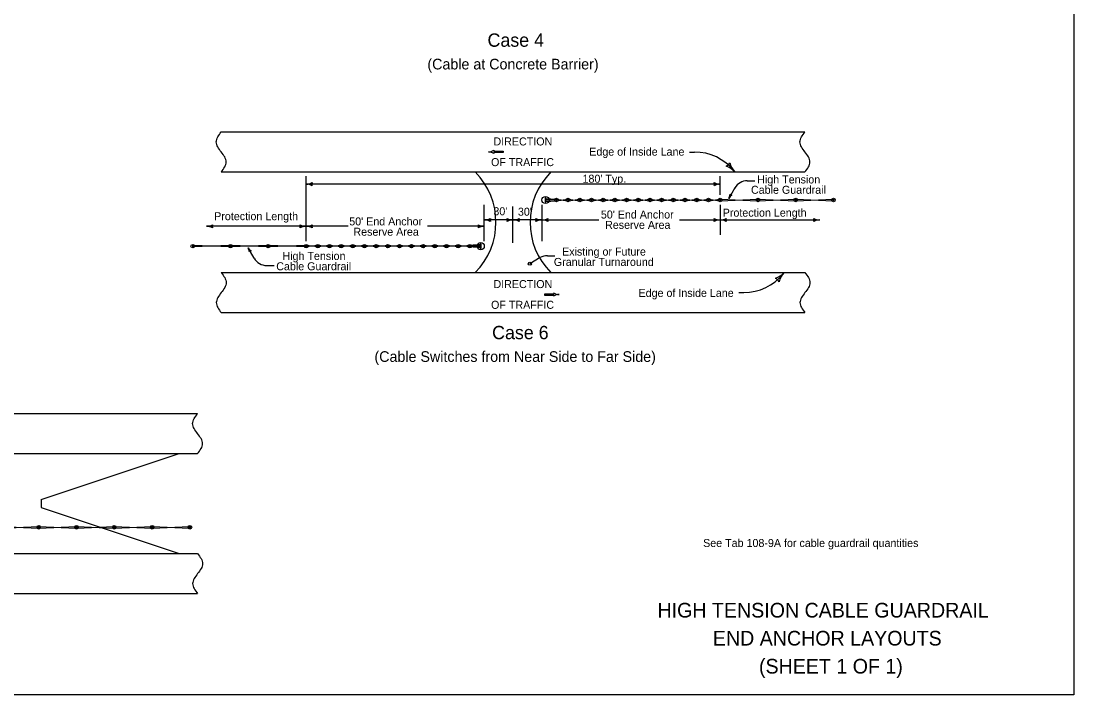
# Model space of a CAD drawing. Extents: x 10133 to 81668, y 7924 to 11018.
# Drawn here: x 11688 to 13268, y 7924 to 8935 of the extents above; entities that cross this region are included whole.
import ezdxf

# ---------------------------------------------------------------- set-up
doc = ezdxf.new("R2010")
doc.units = 0
for name, color, linetype in [('dsnCellElements', 7, 'Continuous'), ('dsnShadingGranular', 7, 'Continuous'), ('DsnShtRevisedText', 7, 'Continuous'), ('dsnStdDimension', 7, 'Continuous'), ('Level 8', 7, 'Continuous'), ('SheetBorder', 7, 'Continuous')]:
    doc.layers.add(name, color=color, linetype=linetype)

msp = doc.modelspace()

# ---------------------------------------------------------------- linework, layer by layer
at = {"layer": 'dsnCellElements'}
for p, q in [((12474.9, 8668.6), (12491.6, 8667.4)), ((12474.9, 8667.4), (12490.7, 8667.4)), ((12474.9, 8665.2), (12490.7, 8665.2)), ((12474.9, 8664), (12491.6, 8665.2)), ((12491.6, 8665.2), (12508.2, 8667.4)), ((12491.6, 8667.4), (12508.2, 8665.2)), ((12509.2, 8665.2), (12525.8, 8667.4)), ((12509.2, 8667.4), (12525.8, 8665.2)), ((12526.7, 8665.2), (12543.3, 8667.4)), ((12526.7, 8667.4), (12543.3, 8665.2)), ((12544.3, 8665.2), (12560.9, 8667.4)), ((12544.3, 8667.4), (12560.9, 8665.2)), ((12561.8, 8665.2), (12578.4, 8667.4)), ((12561.8, 8667.4), (12578.4, 8665.2)), ((12579.4, 8665.2), (12596, 8667.4)), ((12579.4, 8667.4), (12596, 8665.2)), ((12596.9, 8667.4), (12613.5, 8665.2)), ((12596.9, 8665.2), (12613.5, 8667.4)), ((12614.5, 8665.2), (12631.1, 8667.4)), ((12614.5, 8667.4), (12631.1, 8665.2)), ((12632, 8665.2), (12648.6, 8667.4)), ((12632, 8667.4), (12648.6, 8665.2)), ((12649.5, 8665.2), (12666.2, 8667.4)), ((12649.5, 8667.4), (12666.2, 8665.2)), ((12667.1, 8665.2), (12683.7, 8667.4)), ((12667.1, 8667.4), (12683.7, 8665.2)), ((12684.6, 8665.2), (12701.3, 8667.4)), ((12684.6, 8667.4), (12701.3, 8665.2)), ((12702.2, 8665.2), (12718.8, 8667.4)), ((12702.2, 8667.4), (12718.8, 8665.2)), ((12719.7, 8665.2), (12736.4, 8667.4)), ((12719.7, 8667.4), (12736.4, 8665.2)), ((12737.3, 8665.2), (12793.1, 8667.4)), ((12737.3, 8667.4), (12793.1, 8665.2)), ((12794, 8665.2), (12849.8, 8667.4)), ((12794, 8667.4), (12849.8, 8665.2)), ((12850.7, 8665.2), (12906.5, 8667.4)), ((12850.7, 8667.4), (12906.5, 8665.2)), ((12001.9, 8598.1), (11946.1, 8595.8)), ((12001.9, 8595.8), (11946.1, 8598.1)), ((12058.6, 8598.1), (12002.9, 8595.8)), ((12058.6, 8595.8), (12002.9, 8598.1)), ((12115.3, 8598.1), (12059.6, 8595.8)), ((12115.3, 8595.8), (12059.6, 8598.1)), ((12132.9, 8598.1), (12116.3, 8595.8)), ((12132.9, 8595.8), (12116.3, 8598.1)), ((12150.4, 8598.1), (12133.8, 8595.8)), ((12150.4, 8595.8), (12133.8, 8598.1)), ((12168, 8598.1), (12151.3, 8595.8)), ((12168, 8595.8), (12151.3, 8598.1)), ((12185.5, 8598.1), (12168.9, 8595.8)), ((12185.5, 8595.8), (12168.9, 8598.1)), ((12203.1, 8598.1), (12186.4, 8595.8)), ((12203.1, 8595.8), (12186.4, 8598.1)), ((12220.6, 8598.1), (12204, 8595.8)), ((12220.6, 8595.8), (12204, 8598.1)), ((12238.2, 8598.1), (12221.5, 8595.8)), ((12238.2, 8595.8), (12221.5, 8598.1)), ((12255.7, 8595.8), (12239.1, 8598.1)), ((12255.7, 8598.1), (12239.1, 8595.8)), ((12273.2, 8598.1), (12256.6, 8595.8)), ((12273.2, 8595.8), (12256.6, 8598.1)), ((12290.8, 8598.1), (12274.2, 8595.8)), ((12290.8, 8595.8), (12274.2, 8598.1)), ((12308.3, 8598.1), (12291.7, 8595.8)), ((12308.3, 8595.8), (12291.7, 8598.1)), ((12325.9, 8598.1), (12309.3, 8595.8)), ((12325.9, 8595.8), (12309.3, 8598.1)), ((12343.4, 8598.1), (12326.8, 8595.8)), ((12343.4, 8595.8), (12326.8, 8598.1)), ((12361, 8598.1), (12344.4, 8595.8)), ((12361, 8595.8), (12344.4, 8598.1)), ((12377.7, 8599.3), (12361, 8598.1)), ((12377.7, 8594.7), (12361, 8595.8)), ((12377.7, 8598.1), (12361.9, 8598.1)), ((12377.7, 8595.8), (12361.9, 8595.8)), ((11658.4, 8176.6), (11714.2, 8174.3)), ((11658.4, 8174.3), (11714.2, 8176.6)), ((11715.1, 8176.6), (11770.9, 8174.3)), ((11715.1, 8174.3), (11770.9, 8176.6)), ((11771.8, 8176.6), (11827.6, 8174.3)), ((11771.8, 8174.3), (11827.6, 8176.6)), ((11828.5, 8176.6), (11884.3, 8174.3)), ((11828.5, 8174.3), (11884.3, 8176.6)), ((11885.2, 8176.6), (11941, 8174.3)), ((11885.2, 8174.3), (11941, 8176.6))]:
    msp.add_line(p, q, dxfattribs=at)
for points in [[(12474.3, 8669.3), (12474.3, 8663.3), (12475.5, 8663.3), (12475.5, 8669.3)], [(12490.7, 8667.4), (12490.7, 8665.2), (12491.6, 8665.2), (12491.6, 8667.4)], [(12508.2, 8667.4), (12508.2, 8665.2), (12509.2, 8665.2), (12509.2, 8667.4)], [(12525.8, 8667.4), (12525.8, 8665.2), (12526.7, 8665.2), (12526.7, 8667.4)], [(12543.3, 8667.4), (12543.3, 8665.2), (12544.3, 8665.2), (12544.3, 8667.4)], [(12560.9, 8667.4), (12560.9, 8665.2), (12561.8, 8665.2), (12561.8, 8667.4)], [(12578.4, 8667.4), (12578.4, 8665.2), (12579.4, 8665.2), (12579.4, 8667.4)], [(12596, 8667.4), (12596, 8665.2), (12596.9, 8665.2), (12596.9, 8667.4)], [(12613.5, 8667.4), (12613.5, 8665.2), (12614.5, 8665.2), (12614.5, 8667.4)], [(12631.1, 8667.4), (12631.1, 8665.2), (12632, 8665.2), (12632, 8667.4)], [(12648.6, 8667.4), (12648.6, 8665.2), (12649.5, 8665.2), (12649.5, 8667.4)], [(12666.2, 8667.4), (12666.2, 8665.2), (12667.1, 8665.2), (12667.1, 8667.4)], [(12683.7, 8667.4), (12683.7, 8665.2), (12684.6, 8665.2), (12684.6, 8667.4)], [(12701.3, 8667.4), (12701.3, 8665.2), (12702.2, 8665.2), (12702.2, 8667.4)], [(12718.8, 8667.4), (12718.8, 8665.2), (12719.7, 8665.2), (12719.7, 8667.4)], [(12736.4, 8667.4), (12736.4, 8665.2), (12737.3, 8665.2), (12737.3, 8667.4)], [(12736.4, 8667.4), (12736.4, 8665.2), (12737.3, 8665.2), (12737.3, 8667.4)], [(12793.1, 8667.4), (12793.1, 8665.2), (12794, 8665.2), (12794, 8667.4)], [(12793.1, 8667.4), (12793.1, 8665.2), (12794, 8665.2), (12794, 8667.4)], [(12849.8, 8667.4), (12849.8, 8665.2), (12850.7, 8665.2), (12850.7, 8667.4)], [(12849.8, 8667.4), (12849.8, 8665.2), (12850.7, 8665.2), (12850.7, 8667.4)], [(12906.5, 8667.4), (12906.5, 8665.2), (12907.4, 8665.2), (12907.4, 8667.4)], [(11946.1, 8595.8), (11946.1, 8598.1), (11945.2, 8598.1), (11945.2, 8595.8)], [(12002.9, 8595.8), (12002.9, 8598.1), (12001.9, 8598.1), (12001.9, 8595.8)], [(12002.9, 8595.8), (12002.9, 8598.1), (12001.9, 8598.1), (12001.9, 8595.8)], [(12059.6, 8595.8), (12059.6, 8598.1), (12058.6, 8598.1), (12058.6, 8595.8)], [(12059.6, 8595.8), (12059.6, 8598.1), (12058.6, 8598.1), (12058.6, 8595.8)], [(12116.3, 8595.8), (12116.3, 8598.1), (12115.3, 8598.1), (12115.3, 8595.8)], [(12116.3, 8595.8), (12116.3, 8598.1), (12115.3, 8598.1), (12115.3, 8595.8)], [(12133.8, 8595.8), (12133.8, 8598.1), (12132.9, 8598.1), (12132.9, 8595.8)], [(12151.3, 8595.8), (12151.3, 8598.1), (12150.4, 8598.1), (12150.4, 8595.8)], [(12168.9, 8595.8), (12168.9, 8598.1), (12168, 8598.1), (12168, 8595.8)], [(12186.4, 8595.8), (12186.4, 8598.1), (12185.5, 8598.1), (12185.5, 8595.8)], [(12204, 8595.8), (12204, 8598.1), (12203.1, 8598.1), (12203.1, 8595.8)], [(12221.5, 8595.8), (12221.5, 8598.1), (12220.6, 8598.1), (12220.6, 8595.8)], [(12239.1, 8595.8), (12239.1, 8598.1), (12238.2, 8598.1), (12238.2, 8595.8)], [(12256.6, 8595.8), (12256.6, 8598.1), (12255.7, 8598.1), (12255.7, 8595.8)], [(12274.2, 8595.8), (12274.2, 8598.1), (12273.2, 8598.1), (12273.2, 8595.8)], [(12291.7, 8595.8), (12291.7, 8598.1), (12290.8, 8598.1), (12290.8, 8595.8)], [(12309.3, 8595.8), (12309.3, 8598.1), (12308.3, 8598.1), (12308.3, 8595.8)], [(12326.8, 8595.8), (12326.8, 8598.1), (12325.9, 8598.1), (12325.9, 8595.8)], [(12344.4, 8595.8), (12344.4, 8598.1), (12343.4, 8598.1), (12343.4, 8595.8)], [(12361.9, 8595.8), (12361.9, 8598.1), (12361, 8598.1), (12361, 8595.8)], [(12378.3, 8594), (12378.3, 8600), (12377.1, 8600), (12377.1, 8594)], [(11714.2, 8174.3), (11714.2, 8176.6), (11715.1, 8176.6), (11715.1, 8174.3)], [(11714.2, 8174.3), (11714.2, 8176.6), (11715.1, 8176.6), (11715.1, 8174.3)], [(11770.9, 8174.3), (11770.9, 8176.6), (11771.8, 8176.6), (11771.8, 8174.3)], [(11770.9, 8174.3), (11770.9, 8176.6), (11771.8, 8176.6), (11771.8, 8174.3)], [(11827.6, 8174.3), (11827.6, 8176.6), (11828.5, 8176.6), (11828.5, 8174.3)], [(11827.6, 8174.3), (11827.6, 8176.6), (11828.5, 8176.6), (11828.5, 8174.3)], [(11884.3, 8174.3), (11884.3, 8176.6), (11885.2, 8176.6), (11885.2, 8174.3)], [(11884.3, 8174.3), (11884.3, 8176.6), (11885.2, 8176.6), (11885.2, 8174.3)], [(11941, 8174.3), (11941, 8176.6), (11941.9, 8176.6), (11941.9, 8174.3)]]:
    msp.add_lwpolyline(points, close=True, dxfattribs=at)
for centre, radius in [((12474.9, 8666.3), 5.4), ((12491.2, 8666.3), 2.66), ((12508.7, 8666.3), 2.66), ((12526.3, 8666.3), 2.66), ((12543.8, 8666.3), 2.66), ((12561.4, 8666.3), 2.66), ((12578.9, 8666.3), 2.66), ((12596.5, 8666.3), 2.66), ((12614, 8666.3), 2.66), ((12631.6, 8666.3), 2.66), ((12649.1, 8666.3), 2.66), ((12666.6, 8666.3), 2.66), ((12684.2, 8666.3), 2.66), ((12701.7, 8666.3), 2.66), ((12719.3, 8666.3), 2.66), ((12736.8, 8666.3), 2.66), ((12736.8, 8666.3), 2.66), ((12793.5, 8666.3), 2.66), ((12793.5, 8666.3), 2.66), ((12850.2, 8666.3), 2.66), ((12850.2, 8666.3), 2.66), ((12906.9, 8666.3), 2.66), ((11945.7, 8597), 2.66), ((12002.4, 8597), 2.66), ((12002.4, 8597), 2.66), ((12059.1, 8597), 2.66), ((12059.1, 8597), 2.66), ((12115.8, 8597), 2.66), ((12115.8, 8597), 2.66), ((12133.4, 8597), 2.66), ((12150.9, 8597), 2.66), ((12168.4, 8597), 2.66), ((12186, 8597), 2.66), ((12203.5, 8597), 2.66), ((12221.1, 8597), 2.66), ((12238.6, 8597), 2.66), ((12256.1, 8597), 2.66), ((12273.7, 8597), 2.66), ((12291.2, 8597), 2.66), ((12308.8, 8597), 2.66), ((12326.3, 8597), 2.66), ((12343.9, 8597), 2.66), ((12361.4, 8597), 2.66), ((12377.7, 8597), 5.4), ((11714.7, 8175.5), 2.66), ((11714.7, 8175.5), 2.66), ((11771.4, 8175.5), 2.66), ((11771.4, 8175.5), 2.66), ((11828.1, 8175.5), 2.66), ((11828.1, 8175.5), 2.66), ((11884.8, 8175.5), 2.66), ((11884.8, 8175.5), 2.66), ((11941.5, 8175.5), 2.66)]:
    msp.add_circle(centre, radius, dxfattribs=at)
at = {"layer": 'DsnShtRevisedText'}
for p, q in [((12389.2, 8738.5), (12389.2, 8738.5)), ((12397.3, 8741), (12397.3, 8739.3)), ((12397.3, 8739.3), (12411.3, 8739.3)), ((12411.3, 8737.7), (12397.3, 8737.7)), ((12397.3, 8737.7), (12397.3, 8736)), ((12411.3, 8739.3), (12411.3, 8737.7)), ((12691, 8738.2), (12698.4, 8738.2)), ((12115.8, 8604.5), (12115.8, 8702.1)), ((12736.8, 8673.8), (12736.8, 8702.1)), ((12407.3, 8690.1), (12115.8, 8690.1)), ((12736.8, 8690.1), (12407.3, 8690.1)), ((12777.5, 8695.1), (12788.8, 8695.1)), ((12758.7, 8684.3), (12749.8, 8668.6)), ((12383.1, 8604.5), (12383.1, 8658.8)), ((12425.7, 8602.2), (12425.7, 8656.5)), ((12469.5, 8658.8), (12469.5, 8604.5)), ((12736.8, 8658.8), (12736.8, 8614.1)), ((12092.8, 8626.8), (11966.4, 8626.8)), ((12115.8, 8626.8), (12092.8, 8626.8)), ((12179, 8626.8), (12115.8, 8626.8)), ((12383.1, 8626.8), (12298, 8626.8)), ((12469.5, 8636.4), (12383.1, 8636.4)), ((12469.5, 8636.4), (12554.9, 8636.4)), ((12675.9, 8636.4), (12736.8, 8636.4)), ((12736.8, 8636.4), (12759.1, 8636.4)), ((12759.1, 8636.4), (12886.2, 8636.4)), ((12037.7, 8579), (12028.8, 8594.6)), ((12467, 8579.9), (12451.4, 8570.8)), ((12477.8, 8582.7), (12489.1, 8582.7)), ((12056.5, 8568.1), (12067.8, 8568.1)), ((12487.2, 8525.3), (12473.2, 8525.3)), ((12473.2, 8525.3), (12473.2, 8523.8)), ((12473.2, 8523.8), (12487.2, 8523.8)), ((12487.2, 8527.1), (12487.2, 8525.3)), ((12487.2, 8523.8), (12487.2, 8522)), ((12495.3, 8524.6), (12495.3, 8524.6)), ((12764.9, 8527.5), (12772.4, 8527.5))]:
    msp.add_line(p, q, dxfattribs=at)
msp.add_circle((12451.4, 8570.8), 2.4, dxfattribs=at)
for centre, radius, start, end in [((12388.6, 8754.9), 16.4, 272.352, 302.382), ((12388.6, 8722.1), 16.4, 57.618, 87.648), ((12698.4, 8662), 76.2, 39.0106, 90), ((12740.4, 8728.2), 12.5, 295.2639, 330.7306), ((12782.6, 8730.4), 32.4, 194.9248, 222.9973), ((12293.9, 8632.9), 106.7, 315, 45), ((12558.4, 8632.9), 106.7, 135, 225), ((12735.3, 8686.2), 32.4, 42.9973, 71.0698), ((12115.8, 8709.2), 19.1, 270, 298.0725), ((12115.8, 8670.9), 19.1, 61.9275, 90), ((12131.8, 8690.1), 7.39, 162.2666, 197.7334), ((12720.8, 8690.1), 7.39, 342.2666, 17.7333), ((12736.8, 8709.2), 19.1, 241.9275, 270), ((12736.8, 8670.9), 19.1, 90, 118.0725), ((12777.5, 8673.3), 21.8, 90, 149.7757), ((12738.1, 8675.5), 13.6, 329.7686, 357.8411), ((12761.6, 8661.8), 13.6, 121.6962, 149.7686), ((12755.6, 8678.5), 5.25, 222.0353, 257.502), ((11966.4, 8645.9), 19.1, 270, 298.0725), ((11966.4, 8607.7), 19.1, 61.9275, 90), ((11982.4, 8626.8), 7.39, 162.2666, 197.7334), ((12099.7, 8626.8), 7.39, 342.2666, 17.7333), ((12115.8, 8645.9), 19.1, 241.9275, 270), ((12115.8, 8607.7), 19.1, 90, 118.0725), ((12115.8, 8645.9), 19.1, 270, 298.0725), ((12115.8, 8607.7), 19.1, 61.9275, 90), ((12131.8, 8626.8), 7.39, 162.2666, 197.7334), ((12367.1, 8626.8), 7.39, 342.2666, 17.7333), ((12383.1, 8645.9), 19.1, 241.9275, 270), ((12383.1, 8607.7), 19.1, 90, 118.0725), ((12383.1, 8655.6), 19.1, 270, 298.0725), ((12383.1, 8617.3), 19.1, 61.9275, 90), ((12399.2, 8636.4), 7.39, 162.2666, 197.7334), ((12410.3, 8636.4), 7.39, 342.2666, 17.7333), ((12426.3, 8655.6), 19.1, 241.9275, 270), ((12426.3, 8617.3), 19.1, 90, 118.0725), ((12426.3, 8655.6), 19.1, 270, 298.0725), ((12426.3, 8617.3), 19.1, 61.9275, 90), ((12442.3, 8636.4), 7.39, 162.2666, 197.7334), ((12453.4, 8636.4), 7.39, 342.2666, 17.7333), ((12469.5, 8655.6), 19.1, 241.9275, 270), ((12469.5, 8617.3), 19.1, 90, 118.0725), ((12469.5, 8655.6), 19.1, 270, 298.0725), ((12469.5, 8617.3), 19.1, 61.9275, 90), ((12485.5, 8636.4), 7.39, 162.2666, 197.7334), ((12720.8, 8636.4), 7.39, 342.2667, 17.7334), ((12736.8, 8655.6), 19.1, 241.9275, 270), ((12736.8, 8617.3), 19.1, 90, 118.0725), ((12736.8, 8655.6), 19.1, 270, 298.0725), ((12736.8, 8617.3), 19.1, 61.9275, 90), ((12752.9, 8636.4), 7.39, 162.2666, 197.7334), ((12870.2, 8636.4), 7.39, 342.2667, 17.7334), ((12886.2, 8655.6), 19.1, 241.9275, 270), ((12886.2, 8617.3), 19.1, 90, 118.0725), ((12017.1, 8587.8), 13.6, 2.1589, 30.2314), ((12040.6, 8601.5), 13.6, 210.2314, 238.3038), ((12034.6, 8584.8), 5.25, 102.498, 137.9647), ((12056.5, 8589.9), 21.8, 210.2243, 270), ((12477.7, 8561), 21.8, 89.6565, 119.5443), ((12772.4, 8603.7), 76.2, 270, 320.9894), ((12809.2, 8579.5), 32.4, 288.9302, 317.0027), ((12814.4, 8537.5), 12.5, 29.2694, 64.7361), ((12856.6, 8535.3), 32.4, 137.0027, 165.0752), ((12495.9, 8540.9), 16.4, 237.618, 267.648), ((12495.9, 8508.2), 16.4, 92.352, 122.382)]:
    msp.add_arc(centre, radius, start, end, dxfattribs=at)
at = {"layer": 'dsnStdDimension'}
for p, q in [((11988.5, 8768.3), (12864.1, 8768.3)), ((11988.5, 8708.3), (12864.1, 8708.3)), ((11988.5, 8557.4), (12864.1, 8557.4)), ((11988.5, 8497.4), (12864.1, 8497.4)), ((10468.1, 8345.9), (11953.1, 8345.9)), ((11361.5, 8285.9), (11925.5, 8285.9)), ((11718.5, 8216.9), (11925.5, 8285.9)), ((11925.5, 8285.9), (11953.1, 8285.9)), ((11718.5, 8216.9), (11718.5, 8204.9)), ((11718.5, 8204.9), (11925.5, 8135.9)), ((11361.5, 8135.9), (11925.5, 8135.9)), ((11925.5, 8135.9), (11953.1, 8135.9)), ((10468.1, 8075.9), (11953.1, 8075.9))]:
    msp.add_line(p, q, dxfattribs=at)
for points in [[(11988.5, 8708.3), (11996, 8723.3), (11988.5, 8738.3), (11981, 8753.3), (11988.5, 8768.3)], [(12864.1, 8708.3), (12871.6, 8723.3), (12864.1, 8738.3), (12856.6, 8753.3), (12864.1, 8768.3)], [(11988.5, 8557.4), (11996, 8542.4), (11988.5, 8527.4), (11981, 8512.4), (11988.5, 8497.4)], [(12864.1, 8557.4), (12871.6, 8542.4), (12864.1, 8527.4), (12856.6, 8512.4), (12864.1, 8497.4)], [(11953.1, 8285.9), (11960.6, 8300.9), (11953.1, 8315.9), (11945.6, 8330.9), (11953.1, 8345.9)], [(11953.1, 8135.9), (11960.6, 8120.9), (11953.1, 8105.9), (11945.6, 8090.9), (11953.1, 8075.9)]]:
    msp.add_spline(points, degree=3, dxfattribs=at)
at = {"layer": 'SheetBorder'}
msp.add_lwpolyline([(10132.5, 9944), (13267.5, 9944), (13267.5, 7924), (10132.5, 7924)], close=True, dxfattribs=at)

# ---------------------------------------------------------------- texts
at = {"layer": 'dsnShadingGranular'}
for s, p in [('HIGH TENSION CABLE GUARDRAIL', (12642.8, 8040.1)), ('END ANCHOR LAYOUTS', (12725.9, 7998.1)), ('(SHEET 1 OF 1)', (12795.1, 7956.1))]:
    msp.add_text(s, height=22, dxfattribs=at).set_placement(p)
at = {"layer": 'DsnShtRevisedText'}
for s, p in [('DIRECTION', (12396.8, 8748.1)), ('Edge of Inside Lane', (12540.5, 8732.8)), ('OF TRAFFIC', (12393.2, 8717.1)), ("180' Typ.", (12530.4, 8692.2)), ('High Tension', (12792.4, 8691.1)), ('Cable Guardrail', (12783.1, 8675.6)), ("30'", (12396.7, 8643.4)), ("30'", (12433.5, 8642.7)), ('Protection Length', (11977.9, 8636)), ("50' End Anchor", (12180.5, 8628.2)), ("50' End Anchor", (12557.9, 8638.5)), ('Protection Length', (12740.7, 8641.3)), ('Reserve Area', (12186.7, 8612.7)), ('Reserve Area', (12564.2, 8623)), ('Existing or Future', (12499.7, 8582.9)), ('High Tension', (12080.3, 8576.4)), ('Granular Turnaround', (12487.4, 8567.4)), ('Cable Guardrail', (12071, 8560.9)), ('DIRECTION', (12396.8, 8534.2)), ('Edge of Inside Lane', (12614.4, 8520.9)), ('OF TRAFFIC', (12393.2, 8503.1))]:
    msp.add_text(s, height=12, dxfattribs=at).set_placement(p)
at = {"layer": 'Level 8'}
for s, height, p in [('Case 4', 20, (12387.9, 8896.1)), ('(Cable at Concrete Barrier)', 16, (12297.7, 8862.1)), ('Case 6', 20, (12394.8, 8457.5)), ('(Cable Switches from Near Side to Far Side)', 16, (12218.3, 8423.5)), ('See Tab 108-9A for cable guardrail quantities', 12, (12711.3, 8145.9))]:
    msp.add_text(s, height=height, dxfattribs=at).set_placement(p)

doc.saveas('drawing.dxf')
